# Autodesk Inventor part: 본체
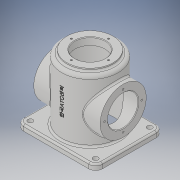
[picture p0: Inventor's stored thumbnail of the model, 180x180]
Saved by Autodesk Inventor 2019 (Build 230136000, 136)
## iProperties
Created: 2020-12
Part Number: 본체
Material: 일반
Document SubType Name: Modeling
Designer: jun-1-15
Density: 1 g/cm^3
Appearance: 기본값
Mass: 457.444 g
Surface Area: 1068.74 cm^2
Volume: 457.444 cm^3
Author: jun-1-15
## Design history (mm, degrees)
sketch "스케치1"
  geometry: C1 r 50 at (0, 0); 1 further point
  constraints: 1 centre point, 1 coincident
  dimensions: "d0" = 100 diameter of C1
extrude "돌출1" new body sketch "스케치1" distance "d1" = 120; taper "d2" = 0 deg
sketch "스케치2"
  geometry: L1 (70, -60)-(-70, -60); L2 (-70, -60)-(-70, 60); L3 (-70, 60)-(70, 60); L4 (70, 60)-(70, -60); L5 (70, -60)-(-70, 60); L6 (-70, -60)-(70, 60); C1 r 50 at (0, 0) reference; 1 further point
  constraints: 12 end point, 2 midpoint, 2 parallel, 1 horizontal, 1 perpendicular
  dimensions: "d3" = 140 distance of L2.end L3.end; "d4" = 120 distance of L1.end L2.end
extrude "돌출2" join sketch "스케치2" distance "d5" = 10; taper "d6" = 0 deg
sketch "스케치3"
  geometry: C1 r 41 at (0, 0); 1 further point
  constraints: 1 centre point, 1 coincident
  dimensions: "d7" = 82 diameter of C1
extrude "돌출3" join sketch "스케치3" distance "d8" = 5; taper "d9" = 0 deg
sketch "스케치4"
  geometry: 2 further points
  constraints: 1 coincident
hole "구멍1" sketch "스케치4" at (0, 0) diameter "d10" = 54; stored, may be unused: countersink angle "d14" = 90 deg, drill point angle "d16" = 0 deg; dims "d11" = 18, "d12" = 84, "d13" = 112, "d15" = 13
node "작업 평면1"
sketch "스케치5"
  geometry: L1 (0, -60)-(0, 60) reference; C1 r 41 at (60, 0); 2 further points
  constraints: 1 centre point, 1 horizontal alignment, 1 midpoint
  dimensions: "d18" = 82 diameter of C1; "d19" = 60 distance from line of L1 C1.centre
extrude "돌출4" join sketch "스케치5" stored distance "d20" = 15; taper "d21" = 0 deg
sketch "스케치7"
  geometry: C1 r 41 at (0, 0) reference; 2 further points
  constraints: 1 vertical alignment
  dimensions: "d29" = 33 distance of C1.centre point (0, 33)
hole "구멍3" sketch "스케치7" at (0, 33) diameter "d30" = 3.242; stored, may be unused: countersink angle "d34" = 90 deg, drill point angle "d36" = 118 deg; dims "d31" = 8, "d32" = 4, "d33" = 2, "d35" = 10
sketch "스케치8"
  geometry: C1 r 41 at (0, 0) reference; 2 further points
  constraints: 1 coincident
hole "구멍4" sketch "스케치8" at (0, 0) diameter "d40" = 54; stored, may be unused: countersink angle "d44" = 90 deg, drill point angle "d46" = 0 deg; dims "d41" = 8, "d42" = 4, "d43" = 2, "d45" = 12
fillet "모깎기1" dims "d47" = 12
sketch "스케치9"
  geometry: 2 further points
  constraints: 1 vertical alignment
  dimensions: "d48" = 33 distance of point (0, 0) point (0, 33)
hole "구멍5" sketch "스케치9" at (0, 33) diameter "d49" = 3.242; stored, may be unused: countersink angle "d53" = 90 deg, drill point angle "d55" = 118 deg; dims "d50" = 8, "d51" = 4, "d52" = 2, "d54" = 10
fillet "모깎기2" dims "d59" = 6
sketch "스케치10"
  geometry: A1 r 12 centre (-58, -48) between (-70, -48) and (-58, -60) reference; 2 further points
  constraints: 1 coincident
hole "구멍6" sketch "스케치10" at (-58, -48) diameter "d60" = 9; stored, may be unused: countersink angle "d64" = 90 deg, drill point angle "d66" = 118 deg; dims "d61" = 8, "d62" = 4, "d63" = 2, "d65" = 10
node "작업 평면3"
sketch "스케치11"
  geometry: L1 (58, 0)-(-58, 0) reference; 3 further points
  constraints: 1 midpoint, 1 vertical alignment, 1 other
  dimensions: "d67" = 70 distance from line of L1 point (0, 70)
feature "엠보싱1" sketch "스케치11" dims "d14" = 90 deg, "d68" = 0.5, "d69" = 0
chamfer "모따기1" distance "d70" = 1; stored, may be unused: second distance "d71" = 2, angle "d72" = 45 deg
fillet "모깎기3" dims "d73" = 3
fillet "모깎기4" dims "d74" = 3
fillet "모깎기5" dims "d75" = 3
fillet "모깎기6" dims "d76" = 3
node "솔리드1"
pattern_circular "원형 패턴1" dims angle "d38" = 360 deg
mirror "미러1"
pattern_circular "원형 패턴2" dims angle "d57" = 360 deg
mirror "미러2"
mirror "미러3"
node "투영된 루프1"
node "투영된 루프2"
other parameters: "d17" = 59
